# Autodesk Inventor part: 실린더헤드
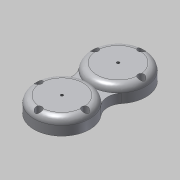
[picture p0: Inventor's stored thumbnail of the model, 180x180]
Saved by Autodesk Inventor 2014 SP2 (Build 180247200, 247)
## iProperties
Created: 2016-11
Part Number: 실린더헤드
Material: 알루미늄 6061
Document SubType Name: Modeling
Designer: mduedu
Density: 2.71 g/cm^3
Mass: 538.448 g
Surface Area: 423.673 cm^2
Volume: 198.689 cm^3
Appearance: 알루미늄 - 평지
Author: mduedu
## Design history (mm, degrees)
sketch "스케치1"
  geometry: C1 r 42 at (0, 0); 1 further point
  constraints: 1 centre point, 1 coincident
  dimensions: "d0" = 84 diameter of C1
extrude "돌출1" new body sketch "스케치1" distance "d1" = 24; taper "d2" = 0 deg
fillet "모깎기1" dims "d3" = 10
sketch "스케치2"
  geometry: C1 r 30 at (0, 0); 1 further point
  constraints: 1 centre point, 1 coincident
  dimensions: "d4" = 60 diameter of C1
extrude "돌출2" join sketch "스케치2" distance "d5" = 5; taper "d6" = 0 deg
sketch "스케치3"
  geometry: C1 r 25 at (0, 0); 1 further point
  constraints: 1 centre point, 1 coincident
  dimensions: "d7" = 50 diameter of C1
extrude "돌출3" cut sketch "스케치3" distance "d8" = 20; taper "d9" = 0 deg
hole "구멍1" diameter "d12" = 4.134; stored, may be unused: countersink angle "d16" = 90 deg, drill point angle "d18" = 118 deg; dims "d10" = 10, "d11" = 10, "d13" = 6, "d14" = 4, "d15" = 2, "d17" = 8
chamfer "모따기1" distance "d19" = 1; stored, may be unused: second distance "d20" = 2, angle "d21" = 45 deg
fillet "모깎기2" dims "d22" = 3
sketch "스케치4"
  geometry: C1 r 17.5 at (0, 0); 1 further point
  constraints: 1 centre point, 1 coincident
  dimensions: "d23" = 35 diameter of C1
extrude "돌출4" cut sketch "스케치4" distance "d24" = 2; taper "d25" = 0 deg
fillet "모깎기3" dims "d26" = 0.5
sketch "스케치5" dims "d32" = 70
  geometry: C1 r 5 at (0, 35); 3 further points
  constraints: 2 coincident, 2 vertical alignment, 1 centre point, 2 other
  dimensions: "d33" = 10 diameter of C1
extrude "돌출5" cut sketch "스케치5" distance "d34" = 10; taper "d35" = 0 deg
sketch "스케치6"
  geometry: A1 r 35 centre (0, -35) between (0, 0) and (-35, -35); 2 further points
  constraints: 3 point on circle, 2 horizontal alignment, 1 centre point, 1 coincident, 1 vertical alignment
  dimensions: "d39" = 70 diameter of A1
hole "구멍3" sketch "스케치6" at (0, 0), (-35, -35), (35, -35) diameter "d57" = 5.5; stored, may be unused: countersink angle "d61" = 90 deg, drill point angle "d63" = 118 deg; dims "d58" = 6, "d59" = 4, "d60" = 2, "d62" = 8
chamfer "모따기2" distance "d54" = 5; stored, may be unused: second distance "d55" = 2, angle "d56" = 30 deg
node "작업 평면1"
sketch "스케치8"
  geometry: L1 (0, 85)-(0, 0); A1 r 42 centre (0, 85) between (-32.469, 58.358) and (32.469, 58.358) reference; A2 r 42 centre (0, 0) between (-32.469, 26.642) and (32.469, 26.642) reference; A3 r 25 centre (51.795, 42.5) between (32.469, 26.642) and (32.469, 58.358); A4 r 25 centre (-51.795, 42.5) between (-32.469, 58.358) and (-32.469, 26.642); A5 r 25 centre (-51.795, 42.5) between (-32.469, 26.642) and (-32.469, 58.358); A6 r 25 centre (51.795, 42.5) between (32.469, 58.358) and (32.469, 26.642); A7 r 42 centre (0, 85) between (-32.469, 58.358) and (32.469, 58.358); A8 r 42 centre (0, 0) between (32.469, 26.642) and (-32.469, 26.642); 1 further point
  constraints: 16 point on circle, 6 centre point, 2 coincident, 2 end point, 2 tangent, 1 symmetric about line, 1 vertical, 1 other
  dimensions: "d65" = 50 diameter of A3
extrude "돌출6" join sketch "스케치8" distance "d67" = 14; taper "d68" = 0 deg
node "솔리드1"
pattern_circular "원형 패턴1" dims angle "d37" = 360 deg
mirror "대칭1"
other parameters: "d64" = 42.5
